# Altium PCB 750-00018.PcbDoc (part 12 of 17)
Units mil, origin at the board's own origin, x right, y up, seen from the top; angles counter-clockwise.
Board outline 7086.64 x 6299.21 mil, 8 copper layers (Top Layer, L2, L3, L4, L5, L6, L7, Bottom Layer), stack 60.6 mil thick; 1356 components, 1054 nets, 4851 pads, 4296 vias.
Unrouted connection lines stored in the file: 12.
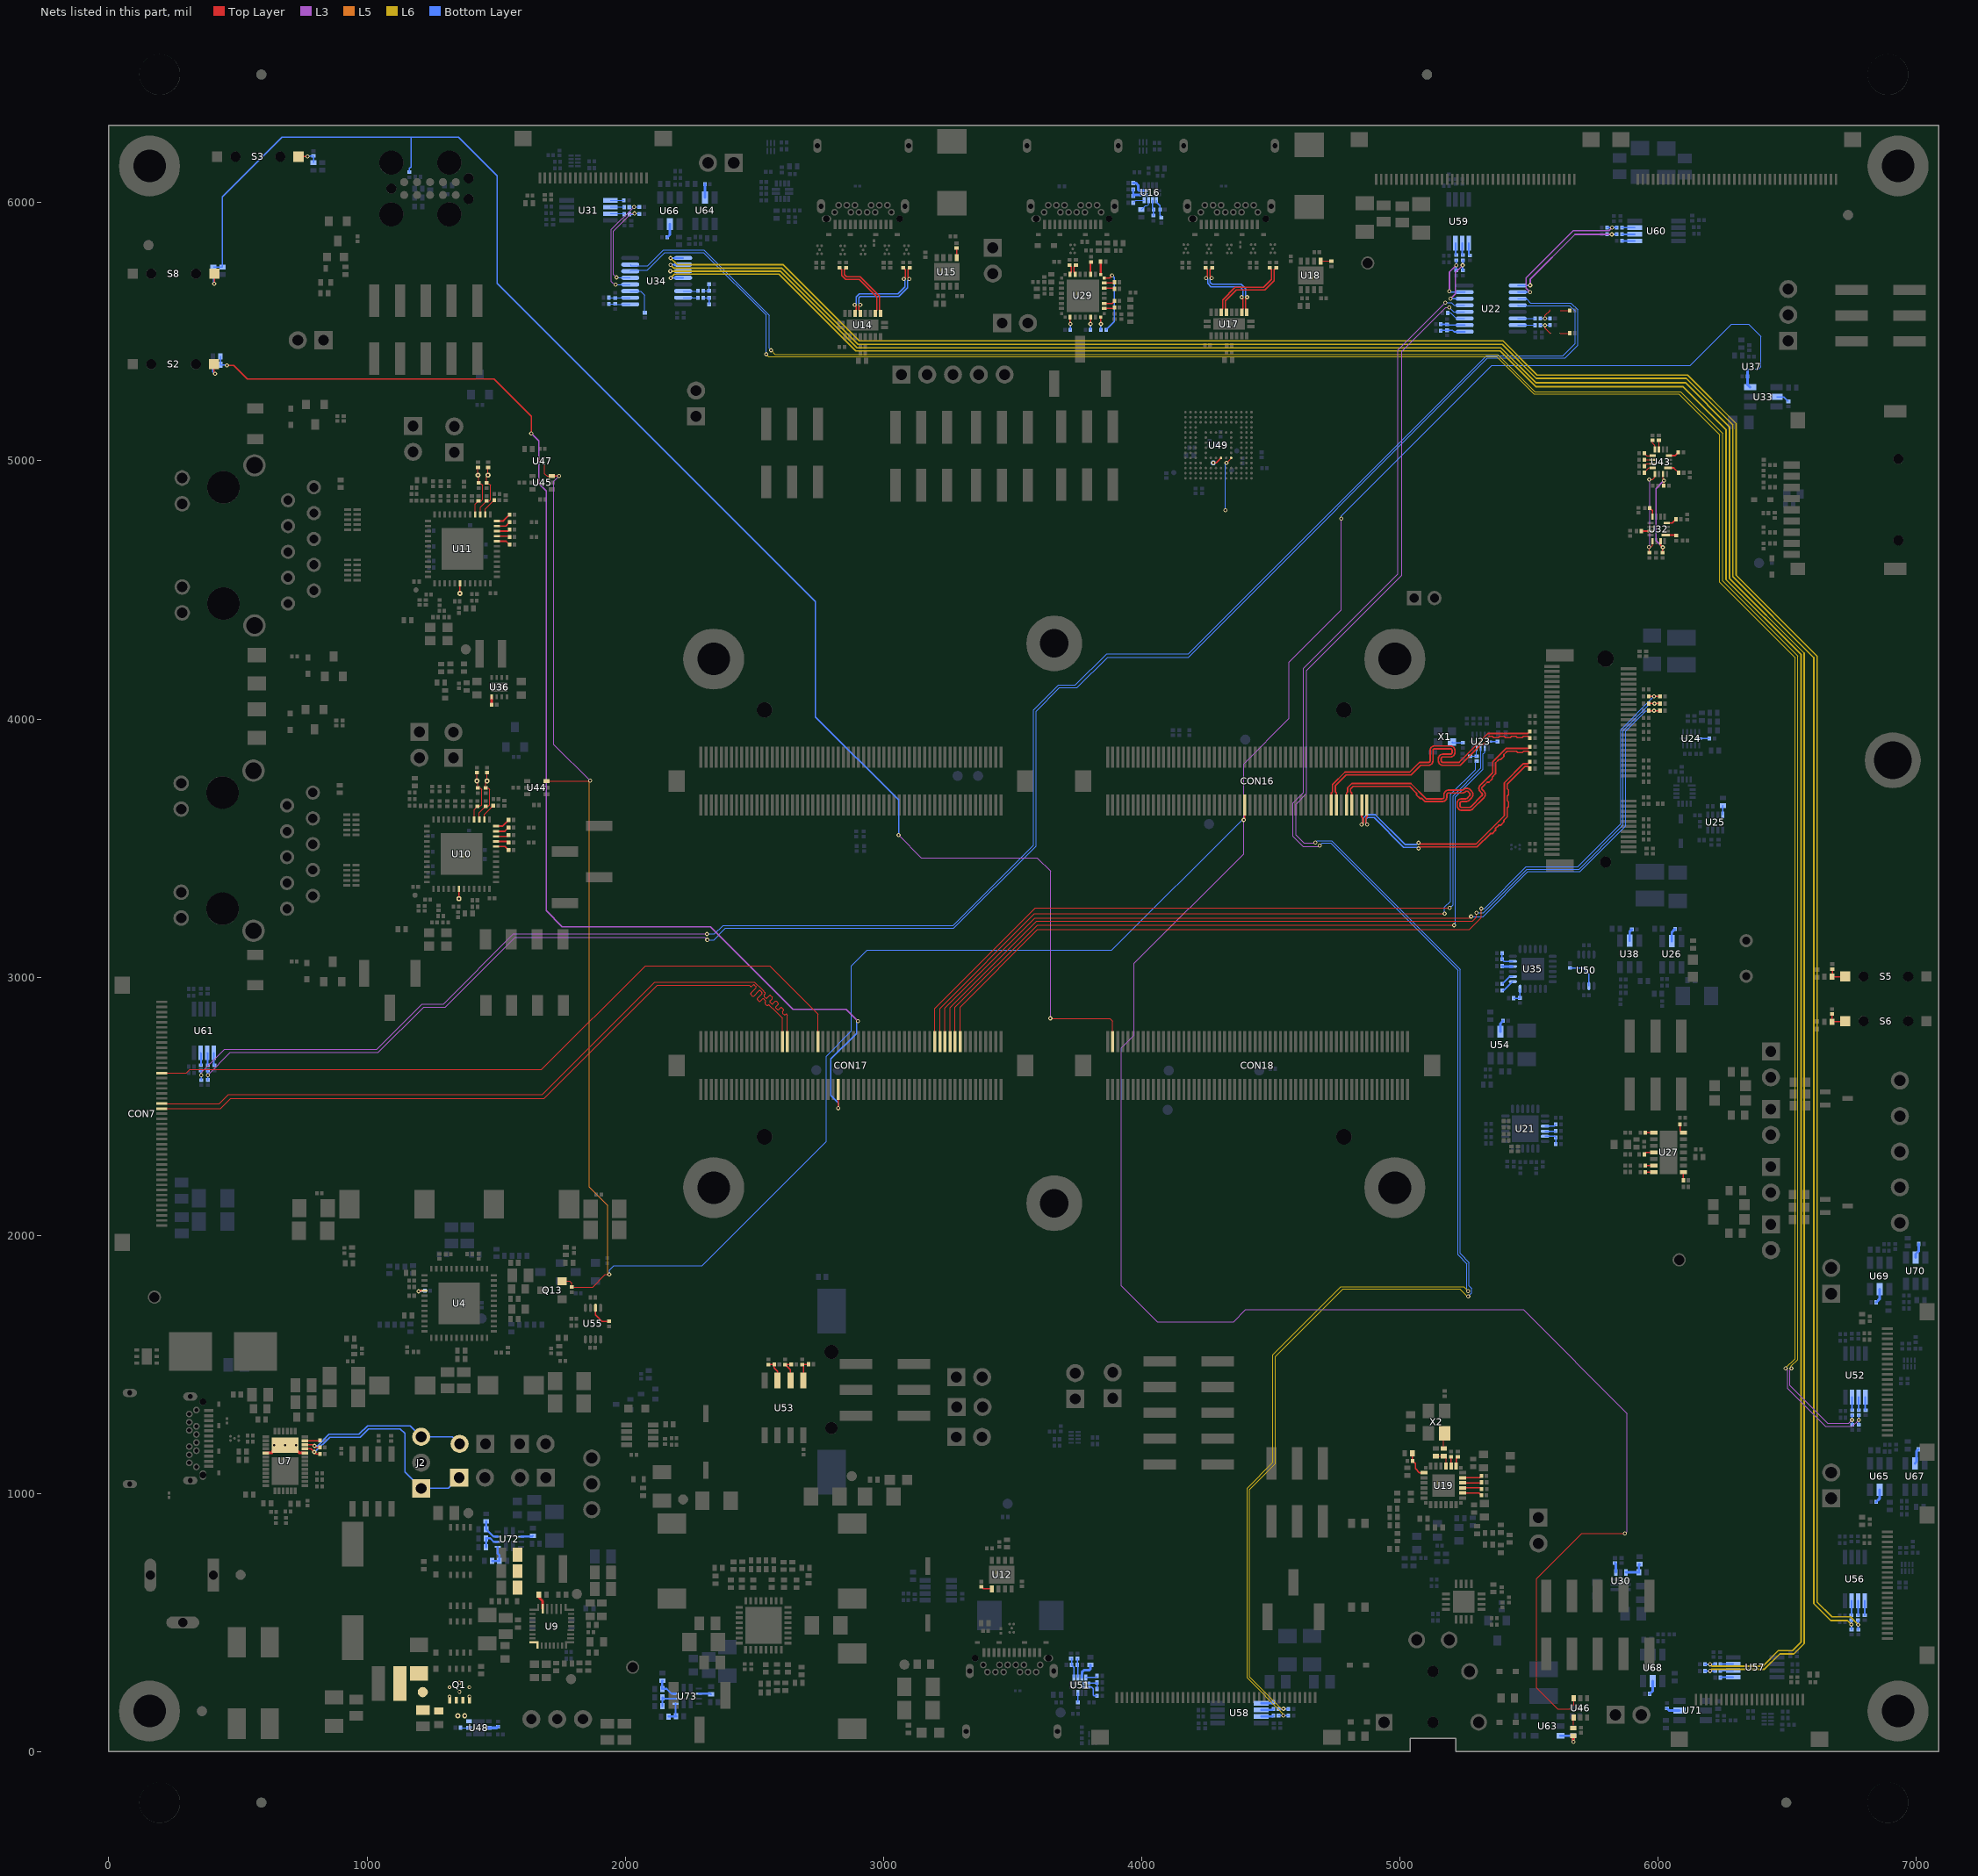
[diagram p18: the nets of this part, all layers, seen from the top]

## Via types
v1: diameter 16, hole 8, Top Layer to Bottom Layer, tented both sides, 3994 vias
v2: diameter 20, hole 10, Top Layer to Bottom Layer, tented both sides, 266 vias
v3: diameter 14, hole 7.87, Top Layer to Bottom Layer, tented both sides, 24 vias
v4: diameter 22, hole 12, Top Layer to Bottom Layer, tented both sides, 8 vias
v5: diameter 24, hole 12, Top Layer to Bottom Layer, tented both sides, 4 vias

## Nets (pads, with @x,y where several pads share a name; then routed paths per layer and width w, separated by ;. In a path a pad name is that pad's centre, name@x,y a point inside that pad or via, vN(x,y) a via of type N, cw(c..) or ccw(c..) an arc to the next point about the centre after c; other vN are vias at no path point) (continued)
NetR162_1: R162.1 R167.2 U16.4 | length 61.9
  Bottom Layer w5: U16.4@4041.55,6008.93 4042.44,6008.04 4042.44,5977.79 R167.2@4046.68,5973.55 4045.78,5972.66 R162.1@4045.78,5949.53
NetR163_1: R163.1 U16.5 | length 51.5
  Bottom Layer w4: R163.1@3999.01,5972.66 4014.91,5988.56 4021.89,5988.56 4025.8,5992.48 U16.5@4025.8,6008.93
NetR164_1: R164.1 R170.2 U16.3 | length 69.9
  Bottom Layer w5: U16.3@4057.29,6008.93 4057.29,6001.57 4070.93,5987.93 R170.2@4070.93,5973.24 4070.93,5951.69 R164.1@4075.93,5946.7
NetR165_1: R165.1 U16.6 | length 46.3
  Bottom Layer w4: R165.1@3967.67,5999.37 3968.2,5999.37 3977.76,6008.93 U16.6@4010.05,6008.93
NetR168_1: R168.1 R171.2 U16.7 | length 68
  Bottom Layer w10: R168.1@3967.03,6025.38 R171.2@3967.03,6050.85 ; R168.1@3967.67,6025.38 3972.88,6030.58 U16.7@4008.08,6030.58
NetR169_1: R169.1 U16.8 | length 63.1
  Bottom Layer w10: R169.1@3967.03,6075.99 3976.65,6075.99 3976.98,6076.31 3985.9,6067.39 3985.9,6051.17 3990.74,6046.33 U16.8@4008.08,6046.33
NetR176_2: R176.2 S2.2 | length 77
  Top Layer w5: S2.2@407.83,5373.93 407.83,5340.18 v1(411.32,5336.69)
  Bottom Layer w5: R176.2@402.59,5371.38 402.59,5345.42 v1(411.32,5336.69)
NetR183_2: R183.2 U19.3 | length 74.3
  Top Layer w5: U19.3@5243.49,1021.9 5312.21,1021.9 R183.2@5316.17,1017.94
NetR184_2: R184.2 U19.2 | length 76.1
  Top Layer w5: U19.2@5243.49,1002.21 5306.62,1002.21 R184.2@5315.76,993.06
NetR185_2: R185.2 U19.5 | length 74.9
  Top Layer w5: U19.5@5243.49,1061.27 5308.12,1061.27 R185.2@5315.35,1068.5
NetR186_2: R186.2 U19.4 | length 73.4
  Top Layer w5: U19.4@5243.49,1041.58 5313.72,1041.58 R186.2@5315.97,1043.83
NetR189_2: R189.2 U19.8 | length 36.2
  Top Layer w5: R189.2@5198.09,1142.7 5198.22,1142.57 U19.8@5198.22,1106.54
NetR190_2: R190.2 U19.7 | length 38.4
  Top Layer w5: U19.7@5217.9,1106.54 5217.9,1136.3 R190.2@5224,1142.4
NetR193_2: R193.2 R199.1 U72.4 | length 84.8
  Bottom Layer w8: R193.2@1460.73,792.73 R199.1@1460.73,826.9 1476.87,826.9 1490.22,813.56 U72.4@1505.8,813.56
NetR200_2: R200.2 R252.1 U73.4 | length 87
  Bottom Layer w8: R200.2@2143.8,176.74 2143.64,176.9 R252.1@2143.64,210.43 2148.48,205.6 U73.4@2194.85,205.6
NetR203_1: R203.1 U46.4 | length 41
  Top Layer w4: R203.1@5672.06,91.55 5672.06,130.8 U46.4@5673.29,132.03
NetR203_2: R203.2 R206.2 U63.3 | length 98.1
  Top Layer w10: v1(5671.94,38.5) 5672.06,38.63 R203.2@5672.06,62.03
  Bottom Layer w10: U63.3@5622.04,61.93 5670.26,61.93 R206.2@5671.34,63.02 5671.34,39.1 v1(5671.94,38.5)
NetR209_2: R209.2 U21.10 | length 42.3
  Bottom Layer w5: U21.10@5562.04,2403.33 5602.63,2403.33 R209.2@5603.85,2404.55
NetR211_2: R211.2 R493.1 U22.4 | length 6884.9
  L3 w4: v1(4672.69,3521.09) 4671.53,3519.93 4628.05,3519.93 4597.15,3550.83 4597.15,3669.84 4638.51,3711.2 4638.51,4188.24 5006.9,4556.62 5006.9,5423.7 5177.13,5593.93 v1(5191.3,5593.93)
  L6 w4: v1(4549.06,166.53) 4541.15,166.53 4417.2,290.47 4417.2,1016.17 4517.14,1116.1 4517.14,1530.31 4778.88,1792.06 5232.16,1792.06 5260.72,1763.5 v1(5264.73,1763.5)
  Bottom Layer w4: v1(4672.69,3521.09) 4679.51,3527.91 4735.96,3527.91 5232.79,3031.08 5232.79,1930.29 5268.08,1895 5268.08,1803.82 5278.08,1793.82 5278.08,1776.85 v1(5264.73,1763.5) ; v1(5191.3,5593.93) 5208.56,5576.68 U22.4@5251.05,5576.68
  Bottom Layer w6: R493.1@4529.88,165.77 4568.52,165.77 R211.2@4568.63,165.88
NetR212_2: R212.2 R494.1 U22.5 | length 6925.5
  L3 w4: v1(4689.67,3509.92) 4686.33,3506.58 4624.82,3506.58 4585.43,3545.98 4585.43,3674.69 4626.79,3716.05 4626.79,4196.77 4992.58,4562.56 4992.58,5429.63 v1(5175.71,5612.77)
  L6 w4: v1(4548.83,140.33) 4548.83,145.23 4408.38,285.68 4408.38,1021.41 4507.46,1120.49 4507.46,1537.86 4770.38,1800.78 5247.15,1800.78 v1(5264.02,1783.91)
  Bottom Layer w4: v1(4689.67,3509.92) 4699.38,3519.63 4731.79,3519.63 5224.31,3027.12 5224.31,1924.45 5258.96,1889.8 5258.96,1788.2 5263.24,1783.91 v1(5264.02,1783.91) ; v1(5175.71,5612.77) 5199.53,5612.77 5210.03,5602.27 U22.5@5251.05,5602.27
  Bottom Layer w6: R494.1@4529.88,140.4 R494.1@4531.84,140.4 ; R494.1@4530.26,139.85 4530.73,140.33 v1(4548.83,140.33) 4568.47,140.33 R212.2@4568.63,140.49
NetR213_2: R213.2 R498.1 U22.6 | length 213.3
  L3 w6: v1(5195.81,5627.74) 5214.93,5646.86 5214.93,5729.5 v1(5243.06,5757.63)
  Bottom Layer w6: v1(5195.81,5627.74) 5218.75,5627.74 U22.6@5218.86,5627.86 ; R213.2@5244.31,5737.11 5243.06,5738.36 v1(5243.06,5757.63) 5244.31,5758.89 R498.1@5244.31,5776.77
NetR214_2: R214.2 R499.1 U22.7 | length 212.3
  L3 w6: v1(5191.59,5656.64) 5191.59,5730.89 v1(5217.88,5757.18)
  Bottom Layer w6: v1(5191.59,5656.64) 5194.78,5653.45 U22.7@5251.05,5653.45 ; R214.2@5218.49,5737.11 5217.88,5737.72 v1(5217.88,5757.18) 5218.49,5757.8 R499.1@5218.49,5776.66
NetR215_2: R215.2 R503.1 U22.9 | length 498.8
  L3 w6: v1(5504.41,5679.62) 5504.41,5703.13 5678.21,5876.94 v1(5820.7,5876.94)
  Bottom Layer w6: U22.9@5456.05,5679.04 5503.83,5679.04 v1(5504.41,5679.62) ; R215.2@5802.11,5877.28 5820.36,5877.28 v1(5820.7,5876.94) 5839.26,5876.94 R503.1@5840.03,5877.71
NetR216_2: R216.2 R504.1 U22.10 | length 560.2
  L3 w6: v1(5503.63,5653.65) 5488.68,5668.6 5488.68,5708.59 5671.2,5891.11 5809.45,5891.11 v1(5821.4,5903.06)
  Bottom Layer w6: U22.10@5456.05,5653.45 5503.44,5653.45 v1(5503.63,5653.65) ; R216.2@5802.24,5903.06 v1(5821.4,5903.06) 5822.13,5903.79 R504.1@5840.03,5903.79
NetR217_2: R217.2 R508.1 U22.11 | length 7215.7
  L3 w4: v1(383.06,2620.61) 470.64,2708.19 1043.08,2708.19 1219.12,2884.23 1303.49,2884.23 1572.98,3153.72 2308.42,3153.72 v1(2317.49,3144.65)
  Bottom Layer w4: v1(2317.49,3144.65) 2343.03,3144.65 2387.74,3189.36 3272.54,3189.36 3590.69,3507.51 3590.69,4030.37 3682.08,4121.76 3749.76,4121.76 3867.69,4239.69 4181.28,4239.69 5339.72,5398.14 5639.69,5398.14 5688.52,5446.97 5688.52,5585.24 5662.36,5611.41 5505.95,5611.41 5489.5,5627.86 U22.11@5456.05,5627.86
  Bottom Layer w6: R508.1@383,2638.86 383,2620.68 v1(383.06,2620.61) 383.06,2602.04 R217.2@383.39,2601.71
NetR218_2: R218.2 R509.1 U22.12 | length 7202.6
  L3 w4: v1(357.55,2620.71) 357.55,2630.35 448.08,2720.88 1037.5,2720.88 1212.64,2896.02 1296.25,2896.02 1567.4,3167.17 v1(2316.56,3167.17)
  Bottom Layer w4: v1(2316.56,3167.17) 2345.46,3167.17 2378.61,3200.33 3270.02,3200.33 3581.15,3511.46 3581.15,4034.32 3678.12,4131.29 3743.38,4131.29 3864.9,4252.82 4180.91,4252.82 5335.39,5407.3 5631.7,5407.3 5678.99,5454.58 5678.99,5580.25 5657.72,5601.51 5456.8,5601.51 U22.12@5456.05,5602.27
  Bottom Layer w6: R509.1@356.73,2638.81 356.73,2621.53 v1(357.55,2620.71) R218.2@357.58,2601.46
NetR219_2: R219.2 R234.1 SB5.2 | length 79.1
  Top Layer w4: v1(5562.14,5551.18) 5562.14,5563.07 5581.59,5582.52 ; 5580.09,5584.03 5581.59,5585.53
  Bottom Layer w4: R234.1@5543.56,5551.18 v1(5562.14,5551.18) 5580.71,5551.18 R219.2@5581.04,5551.51
NetR220_2: R220.2 R255.1 SB6.2 | length 76.9
  Top Layer w4: v1(5562.19,5525.22) 5562.19,5513.81 5581.59,5494.41
  Bottom Layer w4: R255.1@5543.35,5525.22 v1(5562.19,5525.22) 5581.04,5525.22 R220.2@5581.27,5525.46
NetR228_1: R228.1 U23.12 | length 33.7
  Bottom Layer w5: U23.12@5344.43,3912.95 5378.09,3912.95 R228.1@5378.14,3913
NetR229_1: R229.1 U24.12 | length 39.4
  Bottom Layer w5: U24.12@6159.31,3924.27 6198.15,3924.27 R229.1@6198.53,3924.64
NetR230_2: R230.2 U36.5 | length 30.5
  Top Layer w10: R230.2@1482.38,4055.55 U36.5@1482.38,4086.01
NetR233_2: R233.2 U25.8 | length 36
  Bottom Layer w5: U25.8@6250.93,3628.4 6250.93,3663.82 R233.2@6251.33,3664.23
NetR234_2: R234.2 U22.14 | length 67.9
  Bottom Layer w4: U22.14@5456.05,5551.09 5523.79,5551.09 R234.2@5523.88,5551.18
NetR237_1: R237.1 U26.5 | length 50.9
  Bottom Layer w10: U26.5@6053.01,3140.5 6053.01,3174.09 R237.1@6065.26,3186.34
NetR253_1: R253.1 U72.10 | length 46.5
  Bottom Layer w8: U72.10@1596.35,833.24 1638.64,833.24 R253.1@1641.59,836.2
NetR255_2: R255.2 U22.15 | length 67.7
  Bottom Layer w4: U22.15@5456.05,5525.5 5523.39,5525.5 R255.2@5523.66,5525.22
NetR260_2: R260.2 R525.1 U72.3 | length 86
  Bottom Layer w8: R525.1@1484.17,738.96 1484.37,738.76 R260.2@1512.25,738.76 1512.25,761.25 1505.8,767.7 U72.3@1505.8,793.87
NetR271_1: R271.1 U73.10 | length 47.5
  Bottom Layer w8: U73.10@2285.4,225.28 2329.1,225.28 R271.1@2331.78,222.6
NetR272_2: R272.2 R599.1 U73.3 | length 79.1
  Bottom Layer w8: R599.1@2167.96,136.29 2168.6,136.92 R272.2@2196.94,136.92 2194.85,139.01 U73.3@2194.85,185.91
NetR287_1: R287.1 U29.26 | length 50.1
  Top Layer w5: U29.26@3722.76,5556.56 3722.76,5531.15 v1(3723.6,5530.31)
  Bottom Layer w5: R287.1@3723.32,5506.89 3723.32,5530.03 v1(3723.6,5530.31)
NetR290_2: R290.2 U29.7 | length 40.9
  Top Layer w5: U29.7@3854.65,5688.45 3891.4,5688.45 R290.2@3894.34,5691.39
NetR292_1: R292.1 U29.9 | length 49.5
  Top Layer w8: U29.9@3840.88,5721.92 3840.88,5771.31 R292.1@3840.93,5771.36
NetR293_2: R293.2 U29.6 | length 40.9
  Top Layer w5: U29.6@3854.65,5668.77 3891.52,5668.77 R293.2@3894.34,5665.95
NetR294_2: R294.2 U29.3 | length 43.7
  Top Layer w5: U29.3@3854.65,5609.71 3884.83,5609.71 R294.2@3894.37,5619.25
NetR295_1: R295.1 U29.11 | length 49.3
  Top Layer w8: U29.11@3801.5,5721.92 3801.5,5767.74 R295.1@3803.97,5770.21
NetR296_1: R296.1 U29.2 | length 41.3
  Top Layer w5: U29.2@3854.65,5590.03 3890.62,5590.03 R296.1@3894.37,5593.77
NetR297_1: R297.1 U29.30 | length 49.9
  Top Layer w5: U29.30@3801.5,5556.56 3801.5,5530.47 v1(3801.62,5530.36)
  Bottom Layer w5: v1(3801.62,5530.36) 3801.62,5507.27 R297.1@3802,5506.89
NetR298_1: R298.1 U29.8 | length 262.1
  Top Layer w5: U29.8@3854.65,5708.14 3875.06,5708.14 v1@3884.63,5717.71
  Bottom Layer w5: R298.1@3862.2,5506.89 3894.18,5538.87 3894.18,5708.67 v1(3884.89,5717.97)
NetR298_2: R298.2 U29.32 | length 50.4
  Top Layer w5: U29.32@3840.88,5556.56 3840.88,5531.39 v1(3842.06,5530.21)
  Bottom Layer w5: v1(3842.06,5530.21) 3842.06,5507.34 R298.2@3842.51,5506.89
NetR300_2: R300.2 R515.1 U23.4 | length 57
  Bottom Layer w4: R515.1@5271.89,3855.98 R300.2@5297.36,3855.98 ; U23.4@5297.18,3887.36 5297.18,3856.16 R300.2@5297.36,3855.98 ; R300.2@5297.42,3855.92 R300.2@5297.36,3855.98
NetR302_2: R302.2 U21.9 | length 44.7
  Bottom Layer w5: U21.9@5562.04,2423.01 5596.87,2423.01 R302.2@5603.85,2429.99
NetR305_2: R305.2 R392.2 U32.15 U43.15 | length 379.1
  Top Layer w4: U43.15@6018.8,4949.07 6018.8,4926.9 v1(6022.39,4923.3) 6022.39,4904.09 R392.2@6021.85,4903.55
  Top Layer w5: U32.15@6009.56,4688.59 6009.56,4673.36 v1(6018.32,4664.61) 6017.19,4663.47 R305.2@6017.19,4643.83
  L3 w5: v1(6018.32,4664.61) 5990.96,4691.96 5990.96,4891.87 v1(6022.39,4923.3)
NetR306_1: R306.1 U32.1 | length 41.6
  Top Layer w6: U32.1@6029.25,4712.22 6068.72,4712.22 R306.1@6070.24,4710.69
NetR307_1: R307.1 U32.4 | length 41.6
  Top Layer w6: U32.4@6033.19,4759.46 6054.58,4759.46 R307.1@6068.86,4773.74
NetR308_1: R308.1 U32.8 | length 38.7
  Top Layer w6: R308.1@5967.48,4817.39 5978.07,4806.81 U32.8@5978.07,4783.08
NetR310_1: R310.1 U32.11 | length 35.1
  Top Layer w6: R310.1@5935.21,4727.64 5935.54,4727.96 U32.11@5970.19,4727.96
NetR312_1: R312.1 U43.1 | length 48.5
  Top Layer w6: U43.1@6038.48,4972.69 6060.38,4972.69 R312.1@6079.21,4953.85
NetR314_1: R314.1 U43.4 | length 41.1
  Top Layer w6: U43.4@6042.42,5019.93 6065.19,5019.93 6076.19,5030.93 R314.1@6078.16,5032.9
NetR319_1: R319.1 U33.5 | length 53
  Bottom Layer w5: U33.5@6458.49,5247.2 6487.13,5247.2 R319.1@6504.35,5229.97
NetR325_2: R325.2 U29.15 | length 41.4
  Top Layer w5: R325.2@3720.05,5758.16 3727.68,5750.53 3727.68,5731.41 3722.76,5726.49 U29.15@3722.76,5721.92
NetR326_2: R326.2 U12.5 | length 44.7
  Top Layer w5: R326.2@3378.5,639.08 3386.69,630.89 U12.5@3419.82,630.89
NetR328_2: R328.2 U35.20 | length 53.3
  Bottom Layer w5: R328.2@5395.98,2973.64 5396.56,2973.64 5425.25,3002.34 U35.20@5437.38,3002.34
NetR329_2: R329.2 U35.19 | length 54.8
  Bottom Layer w5: R329.2@5396.57,2948.92 5401.87,2948.92 5435.6,2982.66 U35.19@5437.38,2982.66
NetR330_1: R330.1 U35.22 | length 42.1
  Bottom Layer w10: R330.1@5395.93,3043.24 5397.47,3041.71 U35.22@5437.38,3041.71
NetR332_1: R332.1 R335.2 U35.23 | length 68.7
  Bottom Layer w5: R335.2@5395.93,3093.58 R332.1@5395.93,3069.74 5404.28,3061.4 U35.23@5437.38,3061.4
NetR333_1: R333.1 R334.2 U35.18 | length 59.6
  Bottom Layer w5: R334.2@5440.8,2918.88 5463.92,2918.88 R333.1@5464.78,2919.74 5465.18,2920.14 U35.18@5465.18,2954.86
NetR336_1: R336.1 U14.17 | length 358.1
  Top Layer w5: v1(2888.36,5604.54) 2894.83,5598.07 2894.83,5584.96 2890.13,5580.26 U14.17@2890.13,5571.14 ; R336.1@3076.28,5747.72 3084.51,5739.49 3084.51,5710.2 v1(3078.62,5704.31)
  Bottom Layer w5: v1(2888.36,5604.54) 2894.21,5610.39 2894.21,5634.86 2905.56,5646.21 3055.65,5646.21 3083.82,5674.37 3083.82,5699.11 v1(3078.62,5704.31)
NetR337_1: R337.1 U14.16 | length 358
  Top Layer w5: U14.16@2909.81,5571.14 2909.81,5579.51 2904.83,5584.49 2904.83,5599.2 v1(2910.18,5604.54) ; v1(3100.44,5704.31) 3094.51,5710.24 3094.51,5740.39 R337.1@3101.84,5747.72
  Bottom Layer w5: v1(2910.18,5604.54) 2904.21,5610.51 2904.21,5630.72 2909.7,5636.21 3059.79,5636.21 3093.82,5670.23 3093.82,5697.69 v1(3100.44,5704.31)
NetR338_2: R338.2 U15.5 | length 36.8
  Top Layer w5: R338.2@3283.04,5823.96 3283.14,5823.86 U15.5@3283.14,5787.2
NetR339_2: R339.2 U14.13 | length 269.3
  Top Layer w5: R339.2@2829.95,5747.72 2837.65,5740.03 2837.65,5717.52 2853.07,5702.1 2905.99,5702.1 2973.93,5634.17 2973.93,5584.22 2968.87,5579.17 U14.13@2968.87,5571.14
NetR340_2: R340.2 U14.12 | length 269
  Top Layer w5: R340.2@2855.1,5747.72 2847.65,5740.27 2847.65,5721.66 2857.21,5712.1 2910.14,5712.1 2983.93,5638.31 2983.93,5584.57 2988.55,5579.94 U14.12@2988.55,5571.14
NetR341_1: R341.1 U17.17 | length 320.8
  Top Layer w5: U17.17@4308.61,5575.26 4308.61,5583.63 4313.59,5588.61 4313.59,5623.33 4362.16,5671.9 4472.5,5671.9 4502.96,5702.36 4502.96,5740.11 R341.1@4495.34,5747.72
NetR342_1: R342.1 U17.16 | length 320.8
  Top Layer w5: U17.16@4328.29,5575.26 4328.29,5584.37 4323.59,5589.08 4323.59,5619.18 4366.3,5661.9 4476.64,5661.9 4512.96,5698.22 4512.96,5739.79 R342.1@4520.89,5747.72
NetR343_2: R343.2 U18.5 | length 41.5
  Top Layer w4: U18.5@4692.96,5773.25 4734.41,5773.25 R343.2@4734.47,5773.19
NetR344_2: R344.2 U17.13 | length 301.7
  Top Layer w5: R344.2@4247.67,5747.72 4254.76,5740.63 4254.76,5712.95 4250.06,5708.24 v1(4248.97,5708.24) ; v1(4386.51,5634.04) 4392.33,5628.22 4392.33,5588.61 U17.13@4387.35,5583.63
  Bottom Layer w5: v1@4250.06,5708.24 4255.33,5702.97 4255.33,5686.65 4268.77,5673.2 4381.21,5673.2 4392.21,5662.21 4392.21,5639.74 v1(4386.51,5634.04)
NetR345_2: R345.2 U17.12 | length 301.1
  Top Layer w5: v1(4270.79,5708.24) 4264.76,5714.27 4264.76,5739.45 R345.2@4273.03,5747.72 ; U17.12@4407.03,5584.37 4402.33,5589.08 4402.33,5628.04 v1(4408.33,5634.04)
  Bottom Layer w5: v1(4270.79,5708.24) 4265.33,5702.78 4265.33,5690.79 4272.91,5683.2 4385.35,5683.2 4402.21,5666.35 4402.21,5640.16 v1(4408.33,5634.04)
NetR346_1: R346.1 R347.2 U19.13 | length 105.2
  Top Layer w5: R346.1@5048,1156.55 5048.59,1155.95 R347.2@5048.59,1126.3 5059.54,1115.36 5059.54,1097.16 5075.75,1080.95 U19.13@5093.89,1080.95
NetR348_1: R348.1 U22.3 | length 75.2
  Bottom Layer w4: R348.1@5184.82,5572.68 5196.65,5572.68 5218.25,5551.09 U22.3@5251.05,5551.09
NetR349_1: R349.1 U58.5 | length 48.4
  Bottom Layer w8: U58.5@4462.72,188.09 4505.87,188.09 R349.1@4509.57,191.79
NetR350_1: R350.1 U38.5 | length 47.4
  Bottom Layer w10: U38.5@5889.82,3140.94 5889.82,3176.25 R350.1@5898.35,3184.78
NetR351_1: R351.1 X1.3 | length 43.4
  Bottom Layer w5: X1.3@5201.41,3910.98 5204.42,3907.97 R351.1@5243.57,3907.97
NetR355_1: R355.1 U27.14 | length 40.8
  Top Layer w5: R355.1@6084.93,2430.09 6084.93,2404.75 6091.93,2397.75 U27.14@6097.48,2397.75
NetR357_1: R357.1 U27.1 | length 32.9
  Top Layer w5: R357.1@5950.5,2397.48 5950.77,2397.75 U27.1@5983.31,2397.75
NetR358_1: R358.1 U27.4 | length 39.6
  Top Layer w5: R358.1@5946.71,2313.8 5953.88,2320.97 U27.4@5983.31,2320.97
NetR362_1: R362.1 U27.8 | length 30.9
  Top Layer w5: U27.8@6097.48,2244.2 6097.48,2213.42 R362.1@6097.6,2213.3
NetR364_1: R364.1 U27.6 | length 33.3
  Top Layer w5: R364.1@5950.5,2270.91 5951.63,2269.79 U27.6@5983.31,2269.79
NetR365_1: R365.1 U27.7 | length 33.3
  Top Layer w5: R365.1@5950.5,2245.35 5951.66,2244.2 U27.7@5983.31,2244.2
NetR391_2: R391.2 U32.13 U43.13 | length 357.9
  Top Layer w4: v1(5965.63,4927.05) 5978.29,4927.05 5987.3,4936.06 U43.13@5987.3,4949.07 ; R391.2@5966.11,4643.84 5966.11,4663.51 v1(5964.14,4665.47) 5971.28,4665.47 5978.07,4672.26 U32.13@5978.07,4688.59
  L3 w4: v1(5964.14,4665.47) 5967.72,4669.04 5967.72,4924.95 v1(5965.63,4927.05)
NetR393_2: R393.2 U43.7 | length 35.6
  Top Layer w4: U43.7@6003.05,5043.55 R393.2@6003.08,5079.13
NetR394_2: R394.2 R411.1 U34.4 | length 443.8
  L3 w4: v1(1963.01,5681.95) 1962.92,5681.86 1958.84,5681.86 1946.26,5694.44 1946.26,5895.78 v1(2034.16,5983.69)
  Bottom Layer w4: v1(1963.01,5681.95) 1964.13,5683.06 U34.4@2019.09,5683.06 ; R411.1@2015.44,5982.48 2016.64,5983.69 v1(2034.16,5983.69) 2054.02,5983.69 R394.2@2054.42,5983.29
NetR395_1: R395.1 U33.3 U37.4 | length 73.6
  Bottom Layer w10: 6345.65,5353.86 R395.1@6345.65,5326.47 6345.65,5295.09 U33.3@6356.13,5284.6
NetR396_2: R396.2 U43.8 | length 39.4
  Top Layer w4: R396.2@5978.19,5079.13 5978.19,5069.14 5987.3,5060.03 U43.8@5987.3,5043.55
NetR399_2: R399.2 R462.1 U34.5 | length 388.7
  L3 w4: v1(1965.93,5710.19) 1955.02,5721.1 1955.02,5890.22 2023,5958.2 v1(2036.14,5958.2)
  Bottom Layer w4: v1(1965.93,5710.19) 1967.47,5708.66 U34.5@2019.09,5708.66 ; R462.1@2015.59,5955.06 2032.99,5955.06 v1(2036.14,5958.2) 2052.19,5958.2 R399.2@2054.42,5955.97
NetR400_1: R400.1 U31.5 | length 52.3
  Bottom Layer w4: U31.5@1942.62,6008.24 1994.19,6008.24 R400.1@1994.71,6008.77
NetR401_2: R401.2 U29.14 | length 41.4
  Top Layer w5: U29.14@3742.45,5721.92 3742.45,5726.34 3737.68,5731.11 3737.68,5750.65 R401.2@3745.23,5758.2
NetR402_1: R402.1 R404.2 U22.1 | length 95.9
  Bottom Layer w6: R402.1@5158.2,5503.58 5160.03,5505.41 R404.2@5183.08,5505.41 5203.92,5505.41 5209.41,5499.91 U22.1@5251.05,5499.91
NetR403_1: R403.1 R405.2 U22.2 | length 94.4
  Bottom Layer w6: R403.1@5158.3,5529.42 5159,5528.72 R405.2@5183.1,5528.72 5186.32,5525.5 U22.2@5251.05,5525.5
NetR406_2: R406.2 U43.9 | length 37.5
  Top Layer w4: R406.2@5946.06,5029.83 5955.96,5019.93 U43.9@5979.43,5019.93
NetR407_2: R407.2 U43.10 | length 33.3
  Top Layer w4: R407.2@5946.21,5004.45 5946.48,5004.18 U43.10@5979.43,5004.18
NetR411_2: R411.2 U31.6 | length 53.2
  Bottom Layer w4: U31.6@1942.62,5982.65 1995.58,5982.65 R411.2@1995.75,5982.48
NetR412_2: R412.2 U43.11 | length 37
  Top Layer w4: R412.2@5946.35,4979.07 5955.72,4988.43 U43.11@5979.43,4988.43
NetR413_2: R413.2 R533.2 S5.1 | length 80.3
  Top Layer w5: R533.2@6674.43,3031.02 6674.43,3003.03 R413.2@6673.54,3002.13 6723.86,3002.13 S5.1@6724.38,3002.66
NetR414_2: R414.2 R534.2 S6.2 | length 82.2
  Top Layer w5: R534.2@6673.2,2857.29 6673.54,2856.95 R414.2@6673.54,2827.31 6721.51,2827.31 S6.2@6724.38,2830.18
NetR415_2: R415.2 S8.2 | length 76
  Top Layer w5: v1(407.85,5685.54) 408.29,5685.97 S8.2@408.29,5724.88
  Bottom Layer w5: R415.2@405.42,5721.04 405.42,5687.96 v1(407.85,5685.54)
NetR416_1: R416.1 U50.6 | length 129.7
  Bottom Layer w5: R416.1@5658.23,3035.58 5708.79,3035.58 5731.74,3012.63 U50.6@5731.74,2965.91
NetR418_1: R418.1 R419.1 U19.9 | length 71.8
  Top Layer w4: R419.1@5139.83,1144.78 R418.1@5169.61,1144.84 R418.1@5169.61,1144.84 5178.53,1135.91 U19.9@5178.53,1106.54
NetR418_2: R418.2 X2.3 | length 60.7
  Top Layer w4: R418.2@5169.61,1174.36 5169.61,1229.95 X2.3@5173.24,1233.59
NetR428_1: R428.1 R440.2 U21.11 | length 69.1
  Bottom Layer w5: U21.11@5562.04,2383.64 5599.41,2383.64 R440.2@5603.85,2379.21 R428.1@5603.85,2353.77
NetR431_1: R431.1 U54.5 | length 46.5
  Bottom Layer w10: U54.5@5388.7,2788.8 5388.7,2820.44 R431.1@5399.23,2830.97
NetR437_1: R437.1 U55.6 | length 90.5
  Top Layer w5: U55.6@1884.89,1719.36 1884.89,1691.96 1909.79,1667.06 R437.1@1937.66,1667.06
NetR460_2: R460.2 R480.1 R511.2 | length 48.8
  Bottom Layer w4: R480.1@2301.79,5658.15 R511.2@2324.92,5658.2 R511.2@2324.92,5658.2 R460.2@2324.92,5683.86
NetR461_2: R461.2 R479.1 R512.2 | length 49.3
  Bottom Layer w4: R479.1@2301.7,5631.7 R512.2@2324.66,5631.7
  Bottom Layer w6: R512.2@2324.66,5631.7 R512.2@2324.92,5631.45 R461.2@2324.92,5605.46
NetR462_2: R462.2 U31.7 | length 54.1
  Bottom Layer w4: U31.7@1942.62,5957.05 1993.9,5957.05 R462.2@1995.9,5955.06
NetR463_2: R463.2 R467.1 U34.6 | length 8847.7
  L3 w4: v1(6493.89,1484.9) 6501.68,1477.11 6501.68,1406.53 6648.36,1259.85 6752.45,1259.85 v1(6777.55,1284.95)
  L6 w4: v1(2545.95,5412.94) 2555.08,5403.8 5374.48,5403.8 5519.25,5259.03 6079.8,5259.03 6238.43,5100.4 6238.43,4529.67 6501.45,4266.65 6530.11,4237.99 6530.11,1522.1 6493.89,1485.89 v1(6493.89,1484.9)
  Bottom Layer w4: U34.6@2019.09,5734.25 2024.02,5739.17 2084.97,5739.17 2152.79,5807 2303.13,5807 2545.95,5564.18 v1(2545.95,5412.94)
  Bottom Layer w6: R463.2@6777.31,1266.6 6777.55,1266.85 v1(6777.55,1284.95) R467.1@6777.57,1303.48
NetR464_2: R464.2 R478.1 U34.7 | length 8793.1
  L3 w4: v1(6516.06,1484.47) 6510.16,1478.57 6510.16,1418 6656.45,1271.71 6737.41,1271.71 v1(6750.95,1285.25)
  L6 w4: v1(2564.77,5428.18) 2580.49,5412.46 5378.06,5412.46 5522.84,5267.68 6087.57,5267.68 6250.05,5105.21 6250.05,4534.48 6540.96,4243.57 6540.96,1519.59 6516.06,1494.69 v1(6516.06,1484.47)
  Bottom Layer w4: U34.7@2019.09,5759.84 2022.85,5756.07 2087.46,5756.07 2148.64,5817.25 2304.47,5817.25 2557.6,5564.12 2557.6,5435.35 v1(2564.77,5428.18)
  Bottom Layer w6: R464.2@6751.38,1266.61 6751.38,1284.83 v1(6750.95,1285.25) 6750.95,1302.91 R478.1@6751.62,1303.59
NetR465_1: R465.1 U52.5 | length 50.7
  Bottom Layer w6: U52.5@6802.28,1373.42 6802.28,1324.47 R465.1@6803.53,1323.22
NetR466_1: R466.1 U34.3 | length 130.7
  Bottom Layer w4: U34.3@2019.09,5657.47 2059,5657.47 2075.56,5640.92 R466.1@2075.56,5573.51
NetR467_2: R467.2 U52.6 | length 50.6
  Bottom Layer w6: U52.6@6776.69,1373.42 6776.69,1324.05 R467.2@6777.57,1323.17
NetR468_1: R468.1 R470.2 U34.1 | length 83.6
  Bottom Layer w4: R468.1@1936.22,5607.2 1936.69,5607.67 R470.2@1961.1,5607.67 1962.48,5606.29 U34.1@2019.09,5606.29
NetR469_1: R469.1 R471.2 U34.2 | length 83.8
  Bottom Layer w4: R469.1@1936.22,5632.35 1937.63,5630.94 R471.2@1961.1,5630.94 1962.05,5631.88 U34.2@2019.09,5631.88
NetR472_2: R472.2 R475.2 U53.3 | length 90.8
  Top Layer w5: R472.2@2554.1,1499.45 2555.14,1500.49 R475.2@2577.25,1500.49 2577.25,1486.46 2589.85,1473.85 U53.3@2589.85,1438.5
NetR473_2: R473.2 R476.2 U53.2 | length 93.1
  Top Layer w5: U53.2@2639.85,1438.5 2639.85,1479.11 R473.2@2619.51,1499.45 2620.55,1500.49 R476.2@2642.82,1500.49
NetR474_2: R474.2 R477.2 U53.1 | length 88
  Top Layer w5: U53.1@2689.85,1438.5 2689.85,1494.52 R474.2@2684.92,1499.45 2707.9,1499.45 R477.2@2709.3,1500.85
NetR478_2: R478.2 U52.7 | length 50.4
  Bottom Layer w6: U52.7@6751.09,1373.42 6751.09,1323.8 R478.2@6751.62,1323.27
NetR479_2: R479.2 U34.15 | length 58
  Bottom Layer w4: U34.15@2224.09,5631.88 2281.84,5631.88 R479.2@2282.02,5631.7
NetR480_2: R480.2 U34.14 | length 58.3
  Bottom Layer w4: U34.14@2224.09,5657.47 2281.42,5657.47 R480.2@2282.1,5658.15
NetR481_2: R481.2 R484.1 U34.9 | length 9366.6
  L6 w6: v1(2175.63,5785.31) 2201.07,5759.87 2610.94,5759.87 2906.18,5464.63 5399.35,5464.63 5531.55,5332.43 6114.19,5332.43 6302.23,5144.39 6302.23,4556.94 6616,4243.17 6616,914.01 6616,579.68 6673.15,522.53 6744.72,522.53 v1(6774.69,492.56)
  Bottom Layer w6: v1(2175.63,5785.31) 2175.74,5785.43 U34.9@2224.09,5785.43 ; R484.1@6774.32,509.24 6774.32,492.93 v1(6774.69,492.56) 6774.69,473.27 R481.2@6775.03,472.94
NetR482_2: R482.2 R485.1 U34.10 | length 9330.2
  L6 w6: v1(2175.35,5758.61) 2187.5,5746.46 2605.39,5746.46 2900.63,5451.22 5396.29,5451.22 5528.19,5319.32 6108.76,5319.32 6289.12,5138.96 6289.12,4551.51 6602.89,4237.74 6602.89,907.29 6602.89,573.55 6668.06,508.38 6707.22,508.38 6733.11,508.38 v1(6748.46,493.03)
  Bottom Layer w6: v1(2175.35,5758.61) 2176.57,5759.84 U34.10@2224.09,5759.84 ; R485.1@6748.41,509.24 6748.41,493.08 v1(6748.46,493.03) 6749.04,492.45 R482.2@6749.04,473.28
NetR483_1: R483.1 U56.5 | length 56
  Bottom Layer w6: R483.1@6800.12,528.93 6800.25,529.06 U56.5@6800.25,584.91
NetR484_2: R484.2 U56.6 | length 56.1
  Bottom Layer w6: R484.2@6774.32,528.93 6774.66,529.27 U56.6@6774.66,584.91
NetR485_2: R485.2 U56.7 | length 56.3
  Bottom Layer w6: R485.2@6748.41,528.93 6749.06,529.58 U56.7@6749.06,584.91
NetR486_2: R486.2 R489.1 U34.11 | length 9681.5
  L6 w6: v1(2174.58,5734.45) 2600.42,5734.45 2897.44,5437.43 5391.02,5437.43 5525.94,5302.52 6105.07,5302.52 6276.19,5131.4 6276.19,4544.47 6565.66,4255 6565.66,419.17 6525.67,379.18 6471.03,379.18 6411.68,319.83 6208.14,319.83 v1(6201.3,312.99)
  Bottom Layer w6: v1(2174.58,5734.45) 2174.78,5734.25 U34.11@2224.09,5734.25 ; R486.2@6181.57,312.75 6201.06,312.75 v1(6201.3,312.99) 6220.96,312.99 R489.1@6221.34,313.38
NetR487_2: R487.2 R490.1 U34.12 | length 9642.8
  L6 w6: v1(2175.87,5707.43) 2191.13,5722.69 2595.54,5722.69 2892.57,5425.67 5387.72,5425.67 5525.92,5287.47 6096.15,5287.47 6262.69,5120.93 6262.69,4540.56 6553.99,4249.26 6553.99,425.19 6520.49,391.69 6465.43,391.69 6404.77,331.04 6208.42,331.04 v1(6200.93,338.53)
  Bottom Layer w6: v1(2175.87,5707.43) 2177.09,5708.66 U34.12@2224.09,5708.66 ; R487.2@6181.49,338.69 6181.65,338.53 v1(6200.93,338.53) 6201.58,339.18 R490.1@6221.26,339.18
NetR488_1: R488.1 U57.5 | length 50.2
  Bottom Layer w6: R488.1@6241,287.33 6242.26,288.59 U57.5@6290.68,288.59
NetR489_2: R489.2 U57.6 | length 50
  Bottom Layer w6: R489.2@6241.03,313.38 6241.83,314.18 U57.6@6290.68,314.18
NetR490_2: R490.2 U57.7 | length 50
  Bottom Layer w6: R490.2@6240.95,339.18 6241.55,339.78 U57.7@6290.68,339.78
NetR493_2: R493.2 U58.6 | length 48.8
  Bottom Layer w8: U58.6@4462.72,162.5 4506.92,162.5 R493.2@4510.19,165.77
NetR494_2: R494.2 U58.7 | length 48.9
  Bottom Layer w8: U58.7@4462.72,136.9 4506.69,136.9 R494.2@4510.19,140.4
NetR497_1: R497.1 U59.5 | length 48.7
  Bottom Layer w6: U59.5@5266.5,5843.05 5266.5,5800.01 R497.1@5270.49,5796.02
NetR498_2: R498.2 U59.6 | length 48
  Bottom Layer w6: U59.6@5240.91,5843.05 5240.91,5799.87 R498.2@5244.31,5796.46
NetR499_2: R499.2 U59.7 | length 48
  Bottom Layer w6: U59.7@5215.31,5843.05 5215.31,5799.53 R499.2@5218.49,5796.34
NetR502_1: R502.1 U60.5 | length 49.4
  Bottom Layer w6: R502.1@5859.64,5851.81 R502.1@5859.64,5851.81 U60.5@5909.05,5851.76
NetR503_2: R503.2 U60.6 | length 49.5
  Bottom Layer w6: R503.2@5859.72,5877.71 5860.08,5877.35 U60.6@5909.05,5877.35
NetR504_2: R504.2 U60.7 | length 49.7
  Bottom Layer w6: R504.2@5859.72,5903.79 5860.56,5902.95 U60.7@5909.05,5902.95
NetR507_1: R507.1 U61.5 | length 49.8
  Bottom Layer w6: U61.5@406.5,2707.14 406.5,2661.37 R507.1@409.32,2658.55
NetR508_2: R508.2 U61.6 | length 49.5
  Bottom Layer w6: U61.6@380.91,2707.14 383,2705.06 R508.2@383,2658.55
NetR509_2: R509.2 U61.7 | length 49.2
  Bottom Layer w6: U61.7@355.31,2707.14 356.73,2705.73 R509.2@356.73,2658.5
NetR513_2: R513.2 SB5.1 | length 36.5
  Top Layer w4: 5620.96,5582.52 5657.03,5582.52 R513.2@5657.34,5582.21
NetR514_2: R514.2 SB6.1 | length 36.5
  Top Layer w4: 5620.96,5494.41 5657.12,5494.41 R514.2@5657.34,5494.63
NetR524_2: R524.2 U4.40 | length 51.2
  Top Layer w8: v1(1199.31,1783.39) 1202.01,1786.1 U4.40@1222.82,1786.1
  Bottom Layer w8: v1(1199.31,1783.39) 1222.08,1783.39 R524.2@1224.79,1786.1
NetR528_2: R528.2 U43.12 | length 41
  Top Layer w4: R528.2@5946.16,4954.06 5964.78,4972.69 U43.12@5979.43,4972.69
NetR535_2: R535.2 R536.2 S3.1 | length 84.8
  Top Layer w5: S3.1@734.45,6177.92 769.02,6177.92 v1(769.54,6178.44)
  Bottom Layer w5: v1(769.54,6178.44) 771.77,6180.67 R535.2@792.06,6180.67 792.3,6180.44 R536.2@792.3,6154.71
NetR555_2: R555.2 U48.5 | length 31.7
  Bottom Layer w4: R555.2@1361.94,93.34 U48.5@1393.65,93.34
NetR556_1: R556.1 U48.2 | length 37.2
  Bottom Layer w12: U48.2@1471.37,92.38 1501.7,92.38 R556.1@1506.57,97.26
NetR557_1: R557.1 R564.2 U51.3 | length 77.6
  Bottom Layer w5: R557.1@3726.64,360.82 3728.44,359.02 3728.44,336.27 3736.92,327.8 U51.3@3736.92,287.48
NetR558_1: R558.1 R565.2 U51.4 | length 74.4
  Bottom Layer w5: R558.1@3750.73,361.09 3750.73,336.63 R565.2@3751.01,336.35 3752.67,334.7 U51.4@3752.67,287.48
NetR559_1: R559.1 U51.5 | length 75
  Bottom Layer w10: U51.5@3768.41,287.48 3768.41,308.16 3775.7,315.45 3796,315.45 3802.01,321.46 R559.1@3802.01,336.68
NetR561_1: R561.1 U51.6 | length 45.8
  Bottom Layer w5: U51.6@3784.16,287.48 3820.94,287.48 R561.1@3827.3,293.84
NetR562_1: R562.1 R566.2 U51.7 | length 68.4
  Bottom Layer w5: U51.7@3786.13,265.83 3824.35,265.83 R566.2@3827.3,268.79 R562.1@3827.3,242.81
NetR563_1: R563.1 U51.8 | length 68.1
  Bottom Layer w5: U51.8@3786.13,250.08 3805.48,250.08 3812.02,243.54 3812.02,220.86 3815.65,217.24 R563.1@3827.3,217.24
NetR567_2: R567.2 U51.11 | length 37.2
  Bottom Layer w5: U51.11@3752.67,228.43 3752.67,191.52 R567.2@3752.9,191.29
NetR572_1: R572.1 R574.2 U30.9 | length 83.4
  Bottom Layer w10: U30.9@5875.11,694.58 5925.16,694.58 R572.1@5925.48,694.9 5925.48,723.28 R574.2@5928.66,726.46
NetR573_2: R573.2 U30.7 | length 37.5
  Bottom Layer w10: R573.2@5832.86,730.87 5835.74,727.98 U30.7@5835.74,694.58
NetR575_1: R575.1 U64.5 | length 51.8
  Bottom Layer w10: R575.1@2308.37,6071.74 2308.71,6071.4 U64.5@2308.71,6020.04
NetR576_1: R576.1 U65.5 | length 52.3
  Bottom Layer w10: R576.1@6844.7,967.56 6857.25,980.12 U65.5@6857.25,1014.7
NetR581_1: R581.1 U66.5 | length 55.5
  Bottom Layer w10: R581.1@2162.39,5865.61 2172.47,5875.69 U66.5@2172.47,5916.91
NetR582_1: R582.1 U67.5 | length 59.4
  Bottom Layer w10: U67.5@6994.75,1117.23 7001.23,1123.71 7001.23,1165.09 R582.1@7007.52,1171.38
NetR587_1: R587.1 U68.5 | length 54.9
  Bottom Layer w10: R587.1@5967.43,224.12 5979.72,236.41 U68.5@5979.72,273.97
NetR588_1: R588.1 U69.5 | length 55.4
  Bottom Layer w10: R588.1@6844.93,1740.88 6857.25,1753.2 U69.5@6857.25,1791.13
NetR593_1: R593.1 U70.5 | length 57.8
  Bottom Layer w10: U70.5@6997.18,1914.13 6997.18,1927.9 7009.89,1940.6 R593.1@7009.89,1966.65
NetR594_1: R594.1 U71.5 | length 51.7
  Bottom Layer w10: R594.1@6034.01,168.34 6042.05,160.3 U71.5@6082.38,160.3
NetR600_1: R600.1 R602.2 U72.5 | length 87.1
  Bottom Layer w8: R600.1@1461.18,892.02 R600.1@1461.18,892.02 R602.2@1461.13,861.1 1462.01,861.1 1489.87,833.24 U72.5@1505.8,833.24
NetR601_1: R601.1 R604.2 U73.5 | length 90.7
  Bottom Layer w8: R601.1@2144.05,275.2 2143.5,274.65 R604.2@2143.5,243.71 2160.15,243.71 2178.58,225.28 U73.5@2194.85,225.28
NetSB3_1: SB3.1 U49.K5 | length 212.8
  Top Layer w4: v1(4328.53,4991.58) 4346.51,5009.56 U49.K5@4346.51,5011.2
  Bottom Layer w4: v1(4323.6,4808.34) 4323.6,4985.63 4323.09,4986.14 v1(4328.53,4991.58)
NetTP11_1: TP11.1 U10.18 | length 38.7
  Top Layer w5: v1(1355.7,3304.1) U10.18@1355.7,3342.81
NetTP15_1: TP15.1 U11.18 | length 38.7
  Top Layer w5: v1(1359.64,4486.41) U11.18@1359.64,4525.13
NetTP33_1: TP33.1 U49.H5 | length 37.9
  Top Layer w5: v1(4277.21,4991.99) 4287.94,4991.99 U49.H5@4307.14,5011.2
NetU7_15: U7.15 U7.30 U7.40 | length 176.4
  Top Layer w11: U7.30@607.06,1157.37 629.64,1157.37 635.28,1163.01 658.58,1163.01 U7.40@682.85,1187.29 708.95,1187.29 738.87,1157.37 U7.15@758.64,1157.37
  other v1: 640.05,1187.77 682.37,1187.77 725.17,1187.29
PCIe_A_HSI0_N: CON16.96 R281.2 | length 1135.3
  Top Layer w6: CON16.96@4793.31,3666.88 4793.31,3713.58 4797.4,3717.67 4797.4,3733.7 4813.92,3750.22 5042.25,3750.22 5101.38,3691.09 5155.57,3691.09 5164.07,3691.09 ccw(c5164.07,3697.84) 5170.82,3697.84 5170.82,3706.84 cw(c5188.57,3706.84) 5188.57,3724.59 5241.54,3724.59 ccw(c5241.54,3731.34) 5246.3,3726.56 ; 5246.34,3726.6 cw(c5258.9,3714.05) 5271.45,3726.6 5277.81,3720.23 cw(c5265.26,3707.68) 5277.81,3695.13 5267.95,3685.27 cw(c5255.41,3697.84) 5255.41,3680.09 5239.07,3680.09 ccw(c5239.07,3673.34) 5232.32,3673.34 5232.32,3664.34 ccw(c5239.07,3664.34) 5239.07,3657.59 5269.29,3657.59 ccw(c5269.29,3664.34) 5274.06,3659.56 5317.41,3702.92 ccw(c5312.64,3707.68) 5317.42,3712.44 5311.04,3718.82 cw(c5323.6,3731.37) 5311.04,3743.92 ; 5311.06,3743.94 5317.06,3749.93 5359.54,3792.42 5359.54,3834.55 5410.98,3885.99 5497.55,3885.99 R281.2@5504.25,3892.69
PCIe_A_HSI0_P: CON16.98 R283.2 | length 1134.5
  Top Layer w6: CON16.98@4812.99,3666.88 4812.99,3714.09 4808.4,3718.68 4808.4,3729.14 4818.48,3739.22 5037.69,3739.22 5064.3,3712.61 5064.3,3705.54 5077.03,3692.81 5084.1,3692.81 5093.61,3683.31 5096.83,3680.09 5155.57,3680.09 5164.07,3680.09 ccw(c5164.07,3697.84) 5181.82,3697.84 5181.82,3706.84 cw(c5188.57,3706.84) 5188.57,3713.59 5241.54,3713.59 ccw(c5241.54,3731.34) 5254.08,3718.77 5254.14,3718.83 cw(c5258.9,3714.05) 5263.67,3718.82 5270.03,3712.46 cw(c5265.26,3707.68) 5270.03,3702.91 5260.18,3693.06 cw(c5255.41,3697.84) 5255.41,3691.09 5239.07,3691.09 ccw(c5239.07,3673.34) 5221.32,3673.34 5221.32,3664.34 ccw(c5239.07,3664.34) 5239.07,3646.59 5269.29,3646.59 ccw(c5269.29,3664.34) 5281.83,3651.77 5325.2,3695.14 ccw(c5312.64,3707.68) 5325.2,3720.22 5318.82,3726.6 cw(c5323.6,3731.37) 5318.83,3736.15 5324.83,3742.15 5327.81,3745.13 5338.01,3755.34 5345.09,3755.34 5357.81,3768.06 5357.81,3775.13 5370.54,3787.86 5370.54,3830 5383,3842.46 5390.08,3842.46 5402.8,3855.19 5402.8,3862.26 5415.53,3874.99 5451.33,3874.99 5456.33,3869.99 5474.33,3869.99 5479.33,3874.99 5497.33,3874.99 5504.25,3868.06 R283.2@5504.25,3867.07
PCIe_A_HSO0_N: C248.2 CON16.102 | length 1016
  Top Layer w6: v1(4851.65,3591.34) 4856.71,3596.4 4856.71,3615.98 4852.36,3620.33 CON16.102@4852.36,3666.88 ; v1(5072.03,3520.56) 5077.03,3515.56 5294.29,3515.56 5404.3,3625.57 5404.3,3752.32 5479.07,3827.09 5496.45,3827.09 ; C248.2@5497.72,3827.17 C248.2@5504.39,3833.84
  Bottom Layer w6: v1(4851.65,3591.34) 4857.06,3596.75 4857.06,3615.59 4870.52,3629.06 4904.51,3629.06 5019.47,3514.09 5065.56,3514.09 v1(5072.03,3520.56)
PCIe_A_HSO0_P: C249.2 CON16.104 | length 1015.4
  Top Layer w6: CON16.104@4872.05,3666.88 4872.05,3619.97 4867.71,3615.63 4867.71,3597.1 v1(4873.46,3591.34) ; v1(5072.03,3498.74) 5077.85,3504.56 5298.85,3504.56 5350.25,3555.96 5357.32,3555.96 5370.05,3568.69 5370.05,3575.76 5382.77,3588.49 5389.85,3588.49 5402.57,3601.22 5402.57,3608.29 5415.3,3621.02 5415.3,3655.76 5420.3,3660.76 5420.3,3678.76 5415.3,3683.76 5415.3,3701.76 5420.3,3706.76 5420.3,3724.76 5415.3,3729.76 5415.3,3747.76 5483.63,3816.09 5496.45,3816.09 5503.38,3809.16 C249.2@5503.38,3808.17
  Bottom Layer w6: v1(4873.46,3591.34) 4868.06,3596.75 4868.06,3611.04 4875.08,3618.06 4899.95,3618.06 5014.91,3503.09 5067.68,3503.09 v1(5072.03,3498.74)
PCIe_A_PERST#: CON17.26 R300.1 | length 2877.2
  Top Layer w4: CON17.26@3218.51,2750.44 3218.51,2879.57 3585.09,3246.15 v1(5173.24,3246.15)
  Bottom Layer w4: v1(5173.24,3246.15) 5173.24,3271.29 5196.25,3294.3 5196.25,3707.73 5292.7,3804.18 5292.7,3831.52 R300.1@5297.42,3836.23
PCIe_CLKREQ#: CON17.28 U23.3 | length 2952.7
  Top Layer w4: CON17.28@3198.82,2750.44 3198.82,2878.41 3588.68,3268.28 5192.45,3268.28 v1(5192.78,3267.94)
  Bottom Layer w4: v1(5192.78,3267.94) 5205.62,3280.78 5205.62,3702.51 5312.93,3809.82 U23.3@5312.93,3887.36
PCIe_REFCLK_N: CON16.90 R250.2 | length 1134
  Top Layer w6: CON16.90@4734.25,3666.88 4734.25,3713.58 4738.68,3718 4738.68,3745.76 4787.35,3794.43 5038.47,3794.43 5075.86,3831.82 5102.07,3831.82 5110.57,3831.82 ccw(c5110.57,3838.12) 5116.87,3838.12 5116.87,3878.52 cw(c5134.17,3878.52) 5134.17,3895.82 5195.57,3895.82 cw(c5195.57,3878.52) 5212.87,3878.52 5212.87,3870.12 cw(c5195.57,3870.12) 5195.57,3852.82 5166.17,3852.82 ccw(c5166.17,3846.52) 5159.87,3846.52 5159.87,3838.12 ccw(c5166.17,3838.12) 5166.17,3831.82 5222.02,3831.82 5229.01,3831.82 5341.2,3944.02 5496.02,3944.02 R250.2@5503.24,3951.24
PCIe_REFCLK_P: CON16.92 R251.2 | length 1132.3
  Top Layer w6: CON16.92@4753.94,3666.88 4753.94,3714.09 4749.68,3718.35 4749.68,3741.2 4791.91,3783.43 5043.03,3783.43 5080.42,3820.82 5102.07,3820.82 5110.57,3820.82 ccw(c5110.57,3838.12) 5127.87,3838.12 5127.87,3878.52 cw(c5134.17,3878.52) 5134.17,3884.82 5195.57,3884.82 cw(c5195.57,3878.52) 5201.87,3878.52 5201.87,3870.12 cw(c5195.57,3870.12) 5195.57,3863.82 5166.17,3863.82 ccw(c5166.17,3846.52) 5148.87,3846.52 5148.87,3838.12 ccw(c5166.17,3838.12) 5166.17,3820.82 5222.02,3820.82 5233.57,3820.82 5313.23,3900.49 5320.31,3900.49 5333.03,3913.22 5333.03,3920.29 5345.76,3933.02 5358.02,3933.02 5363.02,3928.02 5381.02,3928.02 5386.02,3933.02 5404.02,3933.02 5409.02,3928.02 5427.02,3928.02 5432.02,3933.02 5450.02,3933.02 5455.02,3928.02 5473.02,3928.02 5478.02,3933.02 5496.02,3933.02 R251.2@5503.24,3925.8
PCIe_SM_ALERT#: CON17.18 R160.2 R238.1 | length 3598.1
  Top Layer w4: CON17.18@3297.25,2750.44 3297.25,2884.67 3596.8,3184.22 5268.98,3184.22 5315.01,3230.26 v1(5315.01,3265.67)
  Top Layer w5: R238.1@5963.14,4087.27 v1(5984.06,4087.27) 6006.52,4087.27 R160.2@6007.15,4087.9
  Bottom Layer w4: v1(5315.01,3265.67) 5326.34,3265.67 5488.6,3427.93 5689.91,3427.93 5855.78,3593.8 5855.78,3958.99 v1(5984.06,4087.27)
PCIe_SMCLK: CON17.22 R240.1 R289.2 | length 3614
  Top Layer w4: CON17.22@3257.88,2750.44 3257.88,2882.09 3592.59,3216.81 5280.53,3216.81 5296.9,3233.17 v1(5296.9,3249.72)
  Top Layer w5: R240.1@5965.1,4059.76 v1(5986.03,4059.76) 6007.01,4059.76 R289.2@6007.15,4059.62
  Bottom Layer w4: v1(5296.9,3249.72) 5297.38,3249.25 5322.98,3249.25 5492.42,3418.68 5693.74,3418.68 5865.03,3589.97 5865.03,3955.69 5969.09,4059.76 v1(5986.03,4059.76)
PCIe_SMDAT: CON17.24 R241.1 R299.2 | length 3613.2
  Top Layer w4: CON17.24@3238.19,2750.44 3238.19,2881.33 3586.35,3229.49 5270.1,3229.49 v1(5275.54,3234.93)
  Top Layer w5: R241.1@5963.14,4032.25 v1(5984.06,4032.25) 6007.09,4032.25 R299.2@6007.15,4032.19
  Bottom Layer w4: v1(5275.54,3234.93) 5321.92,3234.93 5495.52,3408.52 5697.95,3408.52 5875.19,3585.76 5875.19,3954.01 5953.43,4032.25 v1(5984.06,4032.25)
PCIe_WAKE#: CON17.20 U23.2 | length 2932.9
  Top Layer w4: CON17.20@3277.56,2750.44 3277.56,2883.45 3595.88,3201.77 v1@5209.86,3201.77
  Bottom Layer w4: v1(5209.86,3200.87) 5214.98,3206 5214.98,3698.94 5322.08,3806.03 5322.08,3864.16 5328.68,3870.76 U23.2@5328.68,3887.36
PD_M_I2C_IRQ: R58.1 U7.18 | length 59.2
  Top Layer w5: U7.18@758.64,1204.61 816.38,1204.61 R58.1@817.41,1205.65
PD_M_I2C_SCL: J2.3 J40.2 R210.1 U7.17 | length 685.8
  Top Layer w5: U7.17@758.64,1188.86 791.43,1188.86 800.84,1179.45 R210.1@817.41,1179.45
  Bottom Layer w5: v1(796.75,1184.77) 808.32,1184.77 852.76,1229.21 968.15,1229.21 1001.78,1262.84 1166.81,1262.84 J2.3@1209.64,1220.01 1331.09,1220.01 J40.2@1358.44,1192.67
PD_M_I2C_SDA: J2.1 J41.1 R273.1 U7.16 | length 865.8
  Top Layer w5: U7.16@758.64,1173.11 783.54,1173.11 v1(795.49,1161.15) 795.49,1160.7 802.61,1153.58 R273.1@817.41,1153.58
  Bottom Layer w5: v1(795.49,1161.15) 798.03,1161.15 855.55,1218.67 974.1,1218.67 1006.06,1250.62 1128.71,1250.62 1146.35,1232.98 1146.35,1083.3 J2.1@1209.64,1020.01 1315.16,1020.01 J41.1@1356.69,1061.54
PER_12V: C112.1 C113.1 C114.1 L9.2 Q1.5 Q1.6 Q1.7 Q1.8 TP4.1 U9.9 U48.6
  other v2: 1352.11,139.07 1378.08,139.62
  other v3: 1319.34,214.2 1396.11,214.2 1357.73,231.99 1319.34,249.83 1396.11,249.83 1357.73,267.62
PHY0_GPIO_0: C124.1 R99.2 R102.1 TP10.1 U10.39 | length 218.2
  Top Layer w4: U10.39@1434.44,3610.53 1434.44,3637.48 C124.1@1459.11,3662.15 1468.92,3662.15 1474.05,3667.28 1474.05,3727.56 1469.14,3732.47 R102.1@1459.11,3732.47 1459.11,3754.6 v1(1464.59,3760.08) 1464.59,3792.1 R99.2@1464.72,3792.23
PHY0_GPIO_1: C125.1 R98.2 R103.1 TP12.1 U10.40 | length 213.6
  Top Layer w4: U10.40@1414.75,3610.53 1414.75,3649.13 C125.1@1427.77,3662.15 1438.26,3662.15 1443.93,3667.81 1443.93,3727.66 1439.77,3731.82 1429.41,3731.82 R103.1@1428.59,3732.64 1428.59,3757.22 v1(1425.73,3760.08) 1425.73,3792.06 R98.2@1425.9,3792.23
PHY0_RX_CLK: R83.2 U10.32 | length 54
  Top Layer w6: U10.32@1499.4,3506.2 1534.73,3506.2 R83.2@1547.94,3492.99
PHY0_RX_CTL: R80.2 U10.38 | length 68.6
  Top Layer w4: U10.38@1454.12,3610.53 1454.12,3630.48 R80.2@1488.49,3664.85
PHY0_RXD0: R84.2 U10.33 | length 50.2
  Top Layer w6: U10.33@1499.4,3525.88 1544.02,3525.88 R84.2@1547.94,3521.96
PHY0_RXD1: R86.2 U10.34 | length 50.8
  Top Layer w6: U10.34@1499.4,3545.57 1542.58,3545.57 R86.2@1547.94,3550.93
PHY0_RXD2: R88.2 U10.35 | length 54.6
  Top Layer w6: U10.35@1499.4,3565.25 1533.3,3565.25 R88.2@1547.94,3579.89
PHY0_RXD3: R89.2 U10.36 | length 58.5
  Top Layer w6: U10.36@1499.4,3584.94 1524.02,3584.94 R89.2@1547.94,3608.86
PHY1_GPIO_0: C150.1 R132.2 R135.1 TP14.1 U11.39 | length 217.9
  Top Layer w4: U11.39@1438.38,4792.84 1438.38,4819.8 C150.1@1463.05,4844.47 1472.86,4844.47 1477.99,4849.6 1477.99,4904.93 1472.43,4910.5 1463.05,4910.5 1463.05,4938.89 v1(1468.53,4944.37) 1468.53,4974.42 R132.2@1468.66,4974.54
PHY1_GPIO_1: C151.1 R131.2 R136.1 TP16.1 U11.40 | length 213.6
  Top Layer w4: U11.40@1418.69,4792.84 1418.69,4831.45 C151.1@1431.72,4844.47 1442.21,4844.47 1447.87,4850.13 1447.87,4905.73 1442.93,4910.67 1432.53,4910.67 1432.53,4941.51 v1(1429.68,4944.37) 1429.68,4954.37 1429.68,4974.37 R131.2@1429.85,4974.54
PHY1_RX_CLK: R116.2 U11.32 | length 54
  Top Layer w6: U11.32@1503.34,4688.51 1538.67,4688.51 R116.2@1551.88,4675.31
PHY1_RX_CTL: R113.2 U11.38 | length 68.6
  Top Layer w4: U11.38@1458.06,4792.84 1458.06,4812.79 R113.2@1492.44,4847.17
PHY1_RXD0: R117.2 U11.33 | length 50.2
  Top Layer w6: U11.33@1503.34,4708.2 1547.96,4708.2 R117.2@1551.88,4704.27
PHY1_RXD1: R119.2 U11.34 | length 50.8
  Top Layer w6: U11.34@1503.34,4727.88 1546.52,4727.88 R119.2@1551.88,4733.24
PHY1_RXD2: R121.2 U11.35 | length 54.6
  Top Layer w6: U11.35@1503.34,4747.57 1537.24,4747.57 R121.2@1551.88,4762.21
PHY1_RXD3: R122.2 U11.36 | length 58.5
  Top Layer w6: U11.36@1503.34,4767.25 1527.96,4767.25 R122.2@1551.88,4791.18
PMID: C99.2 C100.2 C107.2 C108.1 U9.29 | length 59.8
  Top Layer w10: C108.1@1665.29,608.11 1665.29,598.63 1680.14,583.78 U9.29@1680.14,554.47
PWR_BTN#: C304.1 CON17.65 R176.1 | length 5109.6
  Top Layer w5: v1(457.18,5369.9) 483.38,5369.9 536.87,5316.41 1492.37,5316.41 1635.8,5172.97 v1(1635.8,5105.84)
  Top Layer w6: CON17.65@2824.81,2565.4 2824.81,2492.68 v1(2825.03,2492.46)
  L3 w5: v1(1635.8,5105.84) 1664.87,5076.78 1664.87,4911.83 1693.34,4883.35 1693.34,3257.37 1756.11,3194.6 2330.55,3194.6 2649.4,2875.74 2855.26,2875.74 v1(2901.18,2829.82)
  Bottom Layer w5: C304.1@432.04,5404.84 C304.1@432.04,5404.84 R176.1@432.12,5371.38 455.7,5371.38 v1(457.18,5369.9) ; v1(2825.03,2492.46) 2825.03,2513.84 2796.2,2542.67 2796.2,2682.62 2896.15,2782.57 2896.15,2824.8 v1(2901.18,2829.82)
RESET_IN#: C366.1 CON18.118 R415.1 R517.2 | length 6403.8
  Top Layer w4: v1(3646.29,2840.58) 3876.44,2840.58 3887.8,2829.22 CON18.118@3887.8,2750.44
  L3 w4: v1(3058.53,3550.05) 3146.11,3462.47 3595.26,3462.47 3647.38,3410.35 3647.38,2841.67 v1(3646.29,2840.58)
  Bottom Layer w5: R415.1@405.42,5750.57 C366.1@439.61,5750.57 439.61,6021.57 671.11,6253.07 1169.68,6253.07 ; R517.2@1163.83,6118.25 1163.83,6132.66 1169.68,6138.51 1169.68,6253.07 ; v1(3058.53,3550.05) v1(3058.53,3550.05) 3058.62,3685.95 2737.07,4007.5 2737.07,4454.76 1503.69,5688.14 1503.69,6103.39 1354.01,6253.07 1169.68,6253.07
RESET_OUT#: CON16.56 Q13.2 R518.2 U37.2 U44.3 U45.3 U46.3 U47.2 | length 16417.2
  Top Layer w4: U47.2@1687.75,4983.83 1687.75,4949.86 1696.91,4940.7 U45.3@1716.13,4940.7 ; U44.3@1694.67,3760.03 1862.73,3760.03 v1(1863.72,3761.01) ; Q13.2@1755.66,1822.69 1784.92,1822.69 1792.39,1815.22 R518.2@1792.39,1800.17 1873.98,1800.17 1922.21,1848.4 v1(1938.31,1848.4) ; U46.3@5673.29,207.02 5673.29,182.76 5656.58,166.05 5610.49,166.05 5529.49,247.05 5529.49,670.83 5704.76,846.09 5870.2,846.09 v1(5871.07,845.23)
  Top Layer w5: U45.3@1716.13,4940.7 v1@1742.24,4940.7 ; v1(4394.92,3609) 4399.51,3613.59 CON16.56@4399.51,3666.78
  L3 w4: v1(1743.91,4941.13) 1723.7,4920.92 1723.7,3901.03 v1(1863.72,3761.01) ; v1(4772.75,4776.61) 4773.72,4775.64 4773.72,4423.3 4571.39,4220.97 4571.39,4001.89 4394.92,3825.41 v1(4394.92,3609) 4394.92,3478.1 3970.73,3053.9 3970.73,2775.44 3921.75,2726.46 3921.75,1804.5 4061.11,1665.14 4355.81,1665.14 4402.62,1711.95 5477.61,1711.95 5879.01,1310.54 5879.01,853.17 v1(5871.07,845.23)
  L5 w4: v1(1863.72,3761.01) 1860.22,3757.51 1860.22,2187.5 1932.07,2115.64 1932.07,1854.64 v1(1938.31,1848.4)
  Bottom Layer w4: v1(1938.31,1848.4) 1938.31,1865.46 1955.97,1883.11 2298.01,1883.11 2778.05,2363.15 2778.05,2693.94 2876.17,2792.06 2876.17,3044.47 2936.21,3104.51 3883.57,3104.51 4388.06,3609 v1(4394.92,3609) ; v1(4772.75,4776.61) 4772.75,4785.89 5356.37,5369.51 6123.93,5369.51 6284.15,5529.73 6350.31,5529.73 6397.66,5482.38 6397.66,5364.12 6389.21,5355.67 U37.2@6378.18,5355.67
RGB_(PIXEL)CLK: CON7.15 CON17.74 | length 2898.1
  Top Layer w4: CON7.15@204.84,2628.64 299.51,2628.64 312.88,2642 1675.64,2642 2078.23,3044.59 2558.95,3044.59 2746.07,2857.48 CON17.74@2746.07,2750.44
RGB_B0: CON7.22 CON17.88 | length 2876
  Top Layer w4: CON7.22@204.84,2490.84 433.37,2490.84 472.33,2529.8 1685.22,2529.8 2123.7,2968.28 2481.68,2968.28 2483.51,2966.45 2484.93,2965.04 ccw(c2487.76,2967.86) 2490.58,2965.04 2495.02,2969.47 cw(c2497.85,2966.64) 2500.68,2969.47 2506.33,2963.82 cw(c2503.5,2960.99) 2506.33,2958.16 2486.63,2938.45 ccw(c2489.46,2935.62) 2486.63,2932.8 2492.28,2927.14 ccw(c2495.11,2929.97) 2497.94,2927.14 2517.65,2946.84 cw(c2520.48,2944.02) 2523.3,2946.84 2528.96,2941.19 cw(c2526.13,2938.36) 2528.96,2935.53 2511.95,2918.52 ccw(c2514.78,2915.69) 2511.95,2912.87 2517.61,2907.21 ccw(c2520.44,2910.04) 2523.27,2907.21 2531.35,2915.3 cw(c2534.18,2912.47) 2537.01,2915.3 2542.67,2909.64 cw(c2539.84,2906.81) 2542.67,2903.98 2541.49,2902.81 ccw(c2544.32,2899.98) 2541.49,2897.15 2547.15,2891.5 ccw(c2549.98,2894.32) 2552.81,2891.5 cw(c2555.64,2888.67) 2558.47,2891.5 2578.48,2871.48 2579.9,2870.07 2608.27,2841.69 CON17.88@2608.27,2750.44
RGB_B1: CON7.21 CON17.86 | length 2876
  Top Layer w4: CON7.21@204.84,2510.52 428.14,2510.52 462.64,2545.03 1678.28,2545.03 2114.03,2980.78 2500.68,2980.78 2528.55,2952.91 2529.97,2951.5 2541.28,2940.18 cw(c2538.45,2937.35) 2541.28,2934.52 2538.02,2931.26 ccw(c2540.84,2928.43) 2538.02,2925.6 2543.67,2919.95 ccw(c2546.5,2922.78) 2549.33,2919.95 2557.81,2928.43 cw(c2560.64,2925.6) 2563.47,2928.43 2569.13,2922.77 cw(c2566.3,2919.95) 2569.13,2917.12 2560.64,2908.63 ccw(c2563.47,2905.8) 2560.64,2902.98 2566.3,2897.32 ccw(c2569.13,2900.15) 2571.96,2897.32 2580.44,2905.8 cw(c2583.27,2902.98) 2586.1,2905.8 2591.76,2900.15 cw(c2588.93,2897.32) 2591.76,2894.49 2583.27,2886.01 ccw(c2586.1,2883.18) 2583.27,2880.35 2588.93,2874.69 ccw(c2591.76,2877.52) 2594.58,2874.69 2600.87,2880.98 cw(c2603.7,2878.15) 2606.53,2880.98 2612.18,2875.32 cw(c2609.36,2872.49) 2612.18,2869.66 2609.16,2866.64 ccw(c2611.99,2863.81) 2609.16,2860.99 2614.82,2855.33 ccw(c2617.65,2858.16) 2620.48,2855.33 cw(c2623.3,2852.5) 2626.13,2855.33 2627.96,2853.51 2627.96,2844.41 CON17.86@2627.96,2750.44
